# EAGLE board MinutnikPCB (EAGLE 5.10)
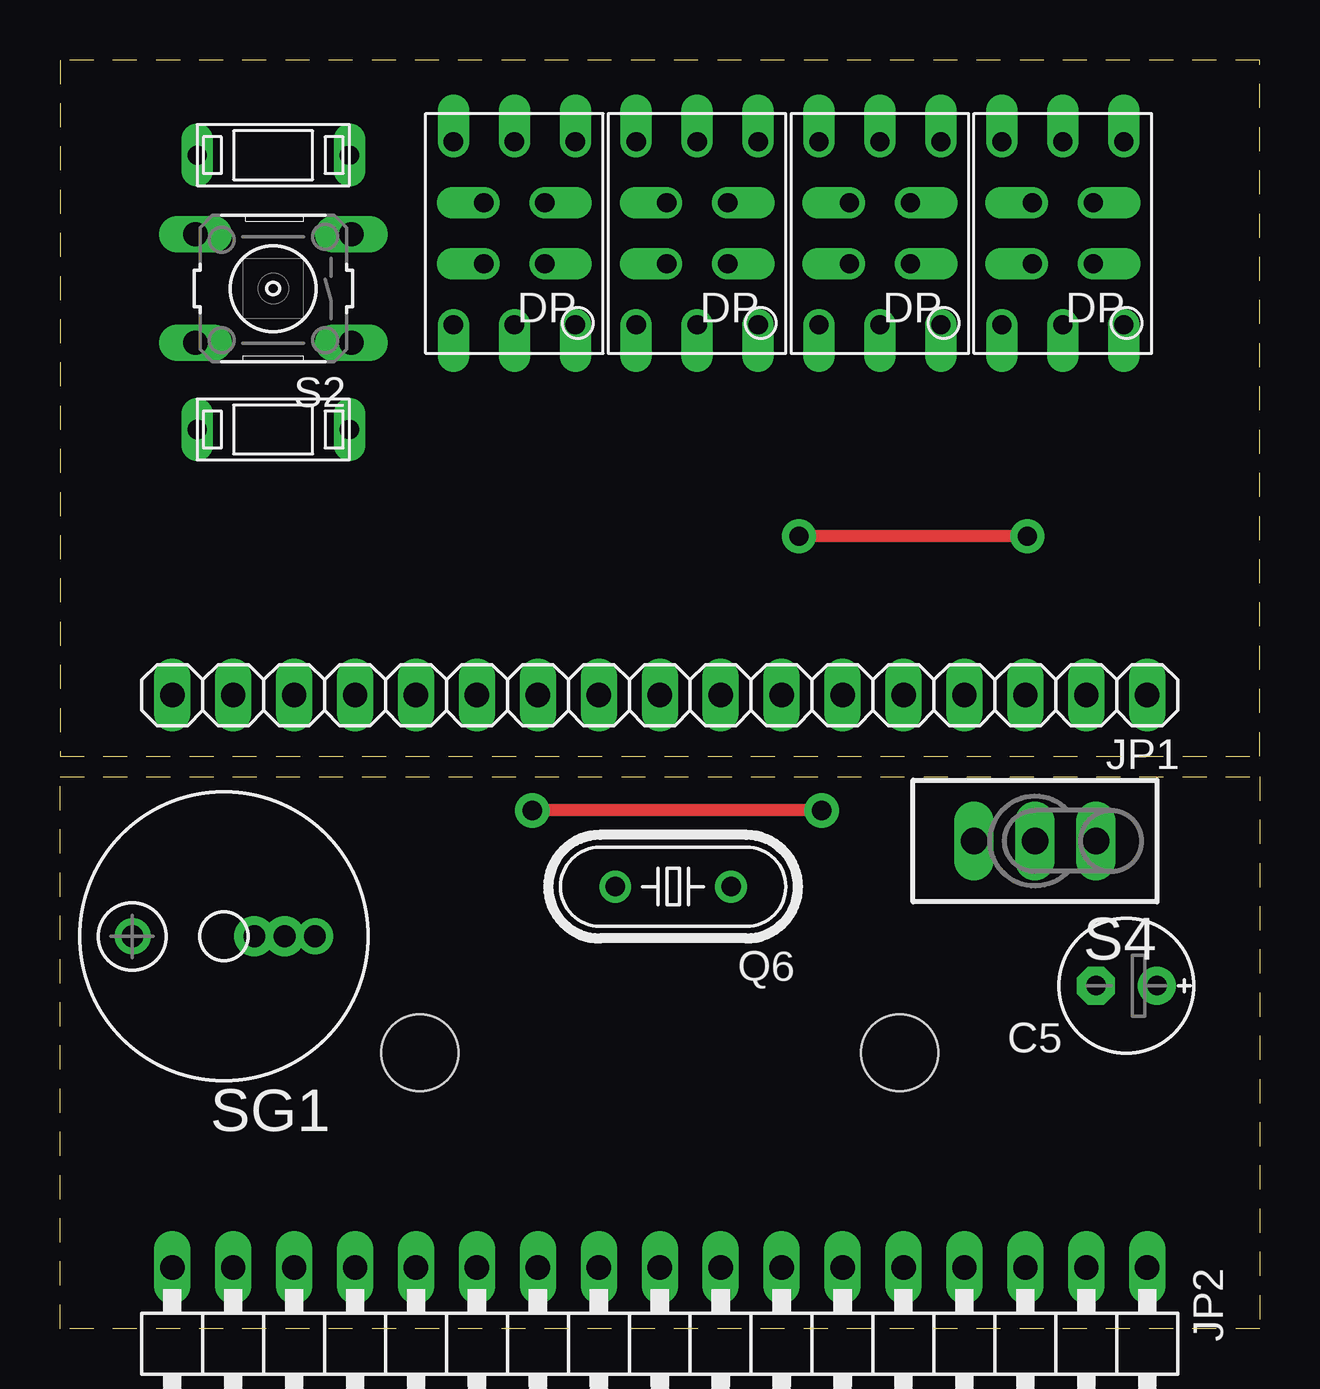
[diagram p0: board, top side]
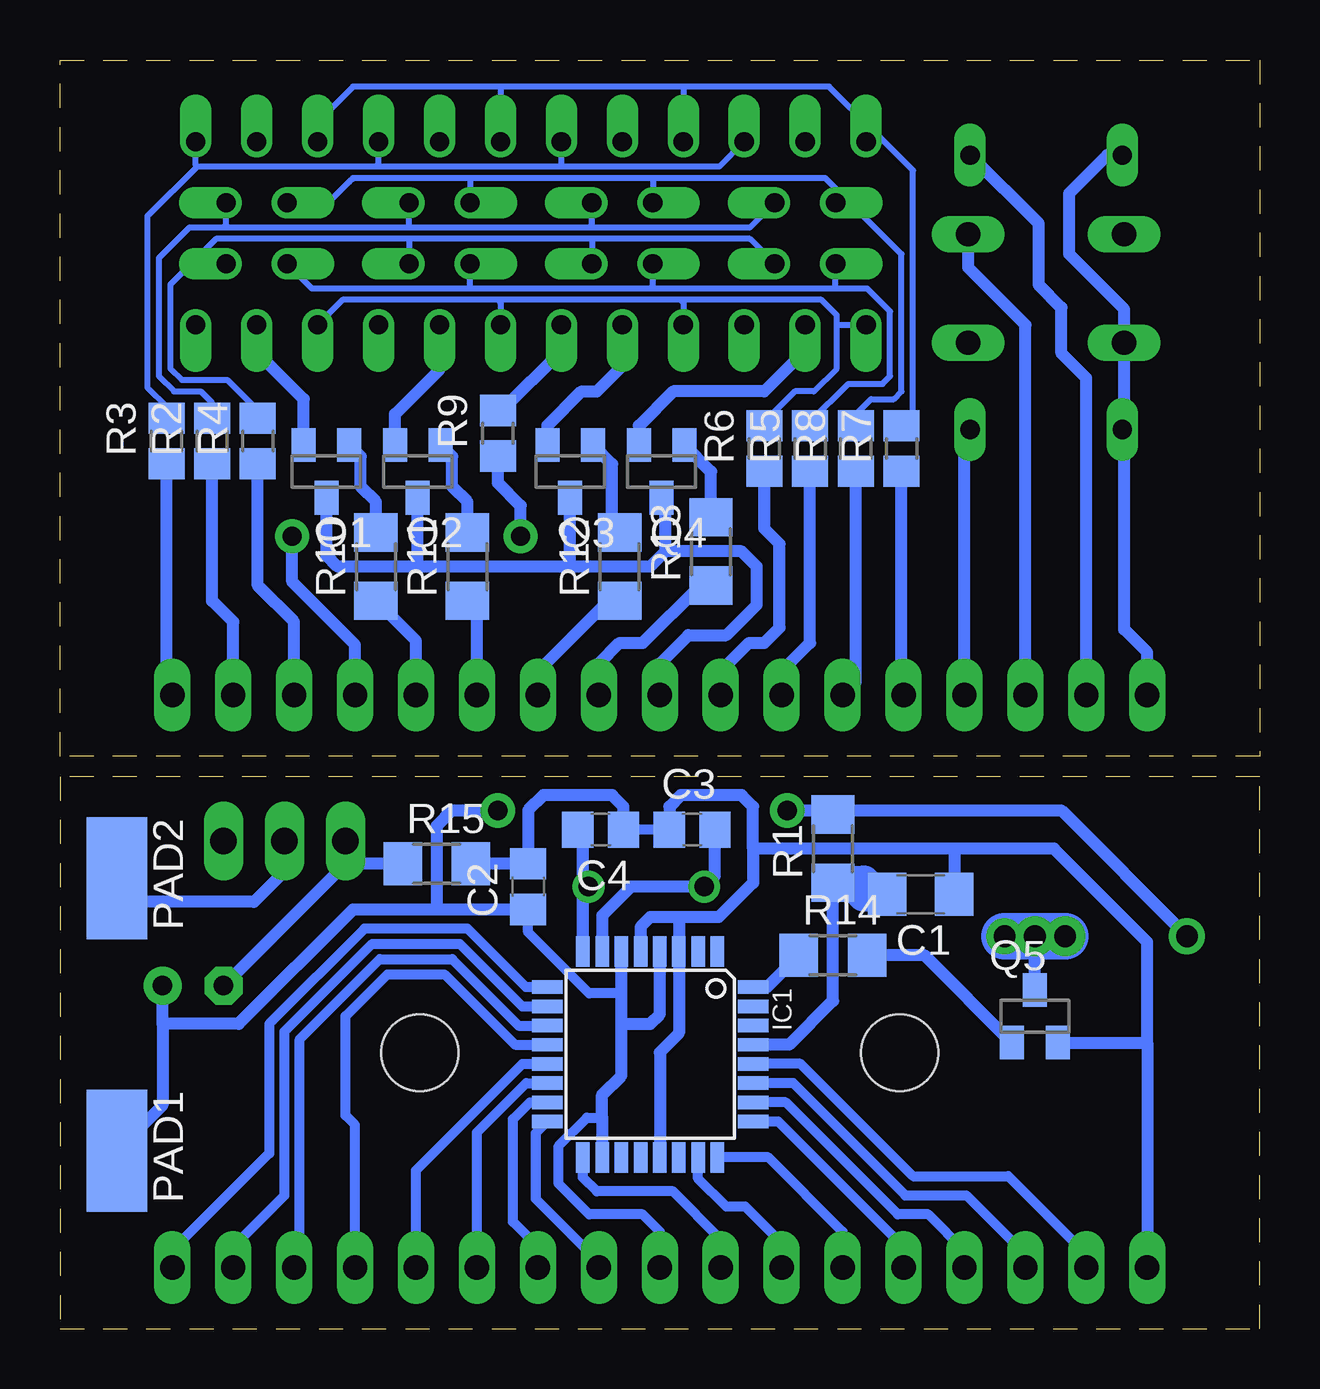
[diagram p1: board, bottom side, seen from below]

Size 50 x 52.86 mm. Coordinates in mm from the lower left corner, seen from the top.
Outline: 0,0 0,23 50,23 50,0 0,0
Outline: 0,23.86 50,23.86 50,52.86 0,52.86 0,23.86
Copper layers (1*16): Top 0.035mm / dielectric 1.5mm / Bottom 0.035mm
Design rules "default *": minimum track width 10mil, minimum drill 24mil, track to track 8mil, track to pad 8mil, pad to pad 8mil, via to via 8mil, smd to smd 8mil, copper to edge 5mil, drill to drill 8mil, minimum pad ring 10mil, minimum via ring 8mil, stop-mask expansion 4mil, vias tented up to drill 0mil, thermal gap 10mil
Holes 3.2 mm at 15,11.5 35,11.5

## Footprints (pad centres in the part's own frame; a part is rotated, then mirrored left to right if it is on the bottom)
C1206 = smd 1.6 x 1.8: 1 -1.4,0; 2 1.4,0
C0805 = smd 1.3 x 1.5: 1 -0.95,0; 2 0.95,0
E2,5-6E = drill 0.813 pad 1.575 round: + -1.27,0 | drill 0.813 pad 1.575 octagon: - 1.27,0
7MM = drill 0.8 pad 1.27 offset: 1 1.16,1.19; 2 2.43,3.73; 3 3.7,1.19; 4 4.97,3.73; 5 6.24,1.19; 6 6.24,8.81; 7 4.97,6.27; 8 3.7,8.81; 9 2.43,6.27; 10 1.16,8.81
TQFP32-08 = smd 1.27 x 0.559: 1 -4.293,2.8; 2 -4.293,2; 3 -4.293,1.2; 4 -4.293,0.4; 5 -4.293,-0.4; 6 -4.293,-1.2; 7 -4.293,-2; 8 -4.293,-2.8; 17 4.293,-2.8; 18 4.293,-2; 19 4.293,-1.2; 20 4.293,-0.4; 21 4.293,0.4; 22 4.293,1.2; 23 4.293,2; 24 4.293,2.8 | smd 0.559 x 1.27: 9 -2.8,-4.293; 10 -2,-4.293; 11 -1.2,-4.293; 12 -0.4,-4.293; 13 0.4,-4.293; 14 1.2,-4.293; 15 2,-4.293; 16 2.8,-4.293; 25 2.8,4.293; 26 2,4.293; 27 1.2,4.293; 28 0.4,4.293; 29 -0.4,4.293; 30 -1.2,4.293; 31 -2,4.293; 32 -2.8,4.293
1X17 = drill 1.016 long: 1 -20.32,0; 2 -17.78,0; 3 -15.24,0; 4 -12.7,0; 5 -10.16,0; 6 -7.62,0; 7 -5.08,0; 8 -2.54,0; 9 0,0; 10 2.54,0; 11 5.08,0; 12 7.62,0; 13 10.16,0; 14 12.7,0; 15 15.24,0; 16 17.78,0; 17 20.32,0
1X17/90 = drill 1.016 long: 1 -20.32,-3.81; 2 -17.78,-3.81; 3 -15.24,-3.81; 4 -12.7,-3.81; 5 -10.16,-3.81; 6 -7.62,-3.81; 7 -5.08,-3.81; 8 -2.54,-3.81; 9 0,-3.81; 10 2.54,-3.81; 11 5.08,-3.81; 12 7.62,-3.81; 13 10.16,-3.81; 14 12.7,-3.81; 15 15.24,-3.81; 16 17.78,-3.81; 17 20.32,-3.81
SMD2,54-5,08 = smd 2.54 x 5.08: 1 0,0
SOT23 = smd 1 x 1.4: 1 -0.95,-1.1; 2 0.95,-1.1; 3 0,1.1
HC49/S = drill 0.813 round: 1 -2.413,0; 2 2.413,0
R1206 = smd 1.6 x 1.803: 1 -1.422,0; 2 1.422,0
R0805 = smd 1.3 x 1.5: 1 -0.95,0; 2 0.95,0
MS = drill 0.8 long: 1 -2.54,0; 2 3.81,0
B3F-10XX = drill 1.016 long: 1 -3.251,2.261; 2 3.251,2.261; 3 -3.251,-2.261; 4 3.251,-2.261
TL3XPO = drill 1.1 pad 1.422 long: 1 -2.54,0; 2 0,0; 3 2.54,0
BMT1205XH7.5 = drill 0.9 pad 1.5 round: + 3.8,0; - -3.8,0

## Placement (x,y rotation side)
C1  100n  [C1206]  14.13,18.1 180 bottom
C2  100n  [C0805]  30.48,18.41 90 bottom
C3  27p  [C0805]  23.65,20.8 0 bottom
C4  27p  [C0805]  27.46,20.8 180 bottom
C5  100u  [E2,5-6E]  44.45,14.29 180 top
DIS1  7MM-CA  [7MM]  38.1,40.64 0 top
DIS2  7MM-CA  [7MM]  30.48,40.64 0 top
DIS3  7MM-CA  [7MM]  22.86,40.64 0 top
DIS4  7MM-CA  [7MM]  15.24,40.64 0 top
IC1  MEGA8-AI  [TQFP32-08]  25.4,11.43 270 bottom
JP1  [1X17]  25,26.4 180 top
JP2  [1X17/90]  25,-1.27 180 top
PAD1  [SMD2,54-5,08]  47.62,7.4 180 bottom
PAD2  [SMD2,54-5,08]  47.62,18.77 180 bottom
Q1  BC846  [SOT23]  38.89,35.72 180 bottom
Q2  BC846  [SOT23]  35.08,35.72 180 bottom
Q3  BC846  [SOT23]  28.73,35.72 180 bottom
Q4  BC846  [SOT23]  24.92,35.72 180 bottom
Q5  BC846  [SOT23]  9.37,13.02 0 bottom
Q6  8 MHz  [HC49/S]  25.56,18.41 180 top
R1  10k  [R1206]  17.78,20 90 bottom
R2  100  [R0805]  43.66,36.99 90 bottom
R3  100  [R0805]  45.56,36.99 90 bottom
R4  100  [R0805]  41.75,36.99 90 bottom
R5  100  [R0805]  18.73,36.67 90 bottom
R6  100  [R0805]  20.64,36.67 90 bottom
R7  100  [R0805]  14.92,36.67 90 bottom
R8  100  [R0805]  16.83,36.67 90 bottom
R9  100  [R0805]  31.75,37.31 90 bottom
R10  4k7  [R1206]  36.83,31.75 90 bottom
R11  4k7  [R1206]  33.02,31.75 90 bottom
R12  4k7  [R1206]  26.67,31.75 90 bottom
R13  4k7  [R1206]  22.86,32.38 90 bottom
R14  4k7  [R1206]  17.78,15.56 0 bottom
R15  0  [R1206]  34.29,19.37 0 bottom
S1  +  [MS]  9.53,37.47 180 top
S2  OK  [B3F-10XX]  8.89,43.34 180 top
S3  -  [MS]  9.53,48.89 180 top
S4  TL32PO  [TL3XPO]  40.64,20.32 180 top
SG1  Piezo  [BMT1205XH7.5]  6.83,16.35 180 top

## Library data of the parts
C1-C5 R1-R15 = rcl
DIS1-DIS4 = led-7-segment
IC1 = atmel
JP1 JP2 = pinhead
PAD1 PAD2 = wirepad
Q1-Q5 = transistor-npn
Q6 = crystal
S1-S3 = switch-omron
S4 = switch
SG1 = buzzer

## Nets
A: DIS1.7 DIS2.7 DIS3.7 DIS4.7 R2.2
A1: DIS1.3 Q1.2
A2: DIS2.3 Q2.2
A3: DIS3.3 Q3.2
A4: DIS4.3 Q4.2
B: DIS1.6 DIS2.6 DIS3.6 DIS4.6 R3.2
C: DIS1.4 DIS2.4 DIS3.4 DIS4.4 R4.2
COM: JP1.17 S1.2 S2.2 S3.2
D: DIS1.2 DIS2.2 DIS3.2 DIS4.2 R5.2
DP: DIS3.5 R9.2
E: DIS1.1 DIS2.1 DIS3.1 DIS4.1 R6.2
F: DIS1.10 DIS2.10 DIS3.10 DIS4.10 R7.2
G: DIS1.9 DIS2.9 DIS3.9 DIS4.9 R8.2
GND: C1.1 C2.2 C3.1 C4.1 IC1.3 IC1.5 IC1.21 JP2.17 Q5.2 R15.2
N$1: C1.2 IC1.29 R1.1
N$2: Q1.1 R10.2
N$3: Q2.1 R11.2
N$5: Q3.1 R12.2
N$6: Q4.1 R13.2
N$7: Q5.3 SG1.-
N$8: IC1.28 JP2.16
N$9: Q5.1 R14.2
N$10: JP1.1 R3.1
N$11: JP1.9 Q1.3 Q2.3 Q3.3 Q4.3
N$12: JP1.2 R2.1
N$13: JP1.3 R4.1
N$14: C3.2 IC1.7 Q6.2
N$15: C4.2 IC1.8 Q6.1
N$16: JP1.7 R12.1
N$17: JP1.5 R10.1
N$18: JP1.6 R11.1
N$19: JP1.8 R13.1
N$20: JP1.4 R9.1
N$21: JP1.10 R6.1
N$22: JP1.11 R5.1
N$23: JP1.12 R8.1
N$24: JP1.13 R7.1
N$25: IC1.27 JP2.15
N$26: IC1.26 JP2.14
N$27: IC1.25 JP2.13
N$28: IC1.24 JP2.12
N$29: IC1.23 JP2.11
N$30: IC1.9 JP2.1
N$31: IC1.10 JP2.2
N$32: IC1.11 JP2.3
N$33: IC1.12 JP2.4
N$34: IC1.13 JP2.5
N$35: IC1.14 JP2.6
N$36: IC1.15 JP2.7
N$37: IC1.17 JP2.10
N$38: IC1.16 JP2.8
N$39: PAD2.1 S4.2
N$40: IC1.32 R14.1
N$41: C5.- R15.1 S4.3
S1: JP1.14 S1.1
S2: JP1.15 S2.3
S3: JP1.16 S3.1
VCC: C2.1 C5.+ IC1.4 IC1.6 IC1.18 JP2.9 PAD1.1 R1.2 SG1.+

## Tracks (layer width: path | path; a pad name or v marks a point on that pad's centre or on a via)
A
  Bottom 0.254: 27.94,45.88 21.24,45.88 DIS4.7 | 27.94,45.88 35.4,45.88 | DIS3.7 27.83,45.99 27.94,45.88 | DIS2.7 35.45,45.93 35.4,45.88 | 35.4,45.88 43.18,45.88 | 43.18,45.88 44.61,45.88 45.88,44.61 45.88,39.69 45.24,39.05 44.13,39.05 43.66,38.58 R2.2 | DIS1.7 43.07,45.99 43.18,45.88
A1
  Bottom 0.508: Q1.2 39.84,38.73 41.8,40.69 DIS1.3
A2
  Bottom 0.508: Q2.2 36.03,38.1 34.18,39.96 DIS2.3
A3
  Bottom 0.508: Q3.2 29.68,37.63 28.26,39.05 27.62,39.05 26.56,40.11 DIS3.3
A4
  Bottom 0.508: DIS4.3 18.94,40.75 20.64,39.05 24.45,39.05 25.87,37.63 Q4.2
B
  Bottom 0.254: 29.05,48.42 22.51,48.42 DIS4.6 | 29.05,48.42 36.83,48.42 | DIS3.6 29.1,48.47 29.05,48.42 | DIS2.6 36.72,48.53 36.83,48.42 | 36.83,48.42 44.29,48.42 | 44.29,48.42 46.35,46.36 46.35,39.21 45.56,38.42 R3.2 | DIS1.6 44.34,48.47 44.29,48.42
C
  Bottom 0.254: 27.78,45.4 21.24,45.4 DIS4.4 | 27.78,45.4 35.4,45.4 | DIS3.4 27.83,45.35 27.78,45.4 | DIS2.4 35.45,45.35 35.4,45.4 | 35.4,45.4 43.5,45.4 44.13,44.77 | 44.13,44.77 45.4,43.5 45.4,40 44.93,39.53 43.02,39.53 41.75,38.26 R4.2 | DIS1.4 43.73,44.37 44.13,44.77
COM
  Bottom 0.508: S3.2 6.35,48.89 7.94,47.31 7.94,44.77 5.64,42.47 S2.2 5.64,37.47 | 5.64,37.47 S1.2 | 5.64,37.47 5.64,29.13 4.68,28.18 JP1.17
D
  Bottom 0.254: 25.4,43.34 32.86,43.34 | 32.86,43.34 39.5,43.34 DIS1.2 | DIS2.2 32.91,43.39 32.86,43.34 | DIS3.2 25.29,43.45 25.4,43.34 | 17.62,43.34 16.35,43.34 15.4,42.39 15.4,39.69 15.72,39.37 17.14,39.37 18.73,37.78 R5.2 | 17.62,43.34 25.4,43.34 | DIS4.2 17.67,43.39 17.62,43.34
DP
  Bottom 0.508: DIS3.5 29.1,40.75 31.59,38.26 R9.2
E
  Bottom 0.254: 24.13,42.86 31.75,42.86 | 31.75,42.86 38.23,42.86 DIS1.1 | DIS2.1 31.64,42.75 31.75,42.86 | DIS3.1 24.02,42.75 24.13,42.86 | 17.62,41.75 17.62,40 18.57,39.05 19.37,39.05 20.64,37.78 R6.2 | DIS4.1 17.54,41.83 17.62,41.75 | 24.13,42.86 18.26,42.86 17.62,42.23 17.62,41.75
F
  Bottom 0.254: 16.11,49.93 17.94,51.75 23.97,51.75 24.02,51.7 | 24.02,51.7 DIS3.10 | 16.11,49.93 14.45,48.26 14.45,38.1 R7.2 | DIS4.10 16.4,49.64 16.11,49.93 | DIS1.10 39.26,50.27 37.78,51.75 31.59,51.75 | 31.59,51.75 24.07,51.75 24.02,51.7 | DIS2.10 31.64,51.7 31.59,51.75
G
  Bottom 0.254: DIS1.9 38.81,46.91 37.94,47.78 | 37.94,47.78 | 37.94,47.78 37.78,47.94 32.86,47.94 | 25.24,47.94 32.86,47.94 | DIS3.9 25.29,47.89 25.24,47.94 | DIS2.9 32.91,47.89 32.86,47.94 | 25.24,47.94 18.1,47.94 17.38,47.23 | 17.38,47.23 14.92,44.77 14.92,39.05 15.24,38.73 16.19,38.73 16.83,38.1 R8.2 16.83,37.47 | DIS4.9 17.67,46.94 17.38,47.23
GND
  Bottom 0.406: C3.1 C4.1
  Bottom 0.508: 24.13,17.14 22.54,17.14 21.11,18.57 21.11,20 | 24.13,17.14 25.4,17.14 25.8,16.74 IC1.5 | 24.13,17.14 24.2,17.07 IC1.3 24.2,12.31 25,11.51 IC1.21 | 21.11,20 21.11,21.75 21.59,22.22 24.13,22.22 24.6,21.75 C3.1 | C4.1 26.51,21.75 26.99,22.22 29.84,22.22 30.48,21.59 C2.2 R15.2 | 12.54,20 21.11,20 | 4.68,11.92 JP2.17 | C1.1 12.73,19.87 12.54,20 | 12.54,20 8.57,20 4.68,16.11 4.68,11.92 | Q5.2 4.68,11.92
N$1
  Bottom 0.508: IC1.29 19.6,11.83 17.78,13.65 R1.1
  Bottom 1.422: R1.1 16.51,18.58 16.51,18.1 C1.2
N$2
  Bottom 0.508: Q1.1 37.47,36.34 37.47,35.08 36.83,34.45 R10.2
N$3
  Bottom 0.508: R11.2 33.02,34.45 33.66,35.08 33.66,36.34 Q2.1
N$5
  Bottom 0.508: Q3.1 26.99,36.02 26.99,33.49 R12.2
N$6
  Bottom 0.508: R13.2 22.86,35.7 Q4.1
N$7  (via drill 0.9 pad 1.68)
  Bottom 0.508: Q5.3 v9.37,16.35 | v9.37,16.35
  Bottom 1.93: SG1.- v8.1,16.35 | v8.1,16.35 | v9.37,16.35 SG1.- | SG1.-
N$8
  Bottom 0.406: IC1.28 19.13,11.03 14.45,6.35 10.48,6.35 7.22,3.09 JP2.16
N$9
  Bottom 0.508: R14.2 13.96,15.56 Q5.1
N$10
  Bottom 0.508: R3.1 45.56,25.64 JP1.1
N$11
  Bottom 0.508: Q1.3 38.89,34.94 38.89,32.23 38.42,31.75 35.08,31.75 | 35.08,31.75 Q2.3 | 35.08,31.75 | Q3.3 28.73,31.75 28.42,31.75 | 28.42,31.75 35.08,31.75 | JP1.9 25,27.7 23.81,28.89 22.23,28.89 20.95,30.16 20.95,31.75 21.59,32.38 24.77,32.38 | 28.42,31.75 25.4,31.75 24.77,32.38 | 24.77,32.38 24.77,34.46 Q4.3
N$12
  Bottom 0.508: R2.1 43.66,30.32 42.78,29.45 JP1.2
N$13
  Bottom 0.508: R4.1 41.75,30.96 40.24,29.45 JP1.3
N$14
  Bottom 0.508: IC1.7 27.4,17.21 26.19,18.41 Q6.2 22.7,18.86 C3.2
N$15
  Bottom 0.508: 28.2,18.41 28.2,20.58 C4.2 | IC1.8 28.2,18.41 | 28.2,18.41 Q6.1
N$16
  Bottom 0.508: 26.35,30.16 R12.1 27.14,30.33 30.08,27.39 JP1.7
N$17
  Bottom 0.508: JP1.5 35.16,28.66 R10.1
N$18
  Bottom 0.508: JP1.6 32.62,29.93 R11.1
N$19
  Bottom 0.508: JP1.8 27.54,27.7 26.67,28.57 25.72,28.57 23.33,30.96 R13.1
N$20  (via drill 0.8 pad 1.42)
  Top 0.508: v40.32,33.02 v30.8,33.02
  Bottom 0.508: R9.1 31.75,35.24 30.8,34.29 v30.8,33.02 | v40.32,33.02 40.32,31.12 37.7,28.49 JP1.4
N$21
  Bottom 0.508: JP1.10 22.46,27.39 21.27,28.57 20.64,28.57 20,29.21 20,32.7 20.64,33.34 R6.1
N$22
  Bottom 0.508: JP1.11 19.92,27.39 18.73,28.57 R5.1
N$23
  Bottom 0.508: R8.1 16.83,26.95 JP1.12
N$24
  Bottom 0.508: R7.1 14.92,25.48 JP1.13
N$25
  Bottom 0.406: IC1.27 19.44,10.23 14.76,5.56 12.22,5.56 9.76,3.09 JP2.15
N$26
  Bottom 0.406: IC1.26 19.75,9.43 15.08,4.76 13.81,4.76 12.3,3.25 JP2.14
N$27
  Bottom 0.406: JP2.13 14.84,3.41 20.06,8.63 IC1.25
N$28
  Bottom 0.406: JP2.12 17.38,4.04 20.47,7.14 IC1.24
N$29
  Bottom 0.406: IC1.23 23.4,6.25 22.23,5.08 21.43,5.08 19.92,3.57 JP2.11
N$30
  Bottom 0.406: IC1.9 30.58,14.23 33.02,16.67 37.31,16.67 41.27,12.7 41.27,7.3 45.32,3.26 JP2.1
N$31
  Bottom 0.406: IC1.10 30.73,13.43 33.34,16.03 36.99,16.03 40.64,12.38 40.64,5.56 42.78,3.42 JP2.2
N$32
  Bottom 0.406: IC1.11 30.89,12.63 33.66,15.4 36.67,15.4 40.01,12.06 40.01,3.81 40.24,3.57 JP2.3
N$33
  Bottom 0.406: IC1.12 31.04,11.83 33.97,14.76 36.35,14.76 38.1,13.02 38.1,8.89 37.7,8.49 JP2.4
N$34
  Bottom 0.406: IC1.13 30.72,11.03 35.16,6.59 JP2.5
N$35
  Bottom 0.406: JP2.6 32.62,8.18 30.57,10.23 IC1.14
N$36
  Bottom 0.406: IC1.15 30.42,9.43 31.11,8.73 31.11,4.45 30.08,3.41 JP2.7
N$37
  Bottom 0.406: JP2.10 22.46,3.73 24.45,5.71 27.62,5.71 28.2,6.29 IC1.17
N$38
  Bottom 0.406: IC1.16 30.16,8.16 30.16,5.4 27.54,2.77 JP2.8
N$39
  Bottom 0.508: S4.2 40.64,19.05 41.91,17.78 46.63,17.78 PAD2.1
N$40
  Bottom 0.508: IC1.32 20.53,14.23 R14.1
N$41
  Bottom 0.508: 38.1,19.37 S4.3 | R15.1 38.1,19.37 | 38.1,19.37 C5.-
S1
  Bottom 0.508: JP1.14 12.3,37.23 S1.1
S2
  Bottom 0.508: JP1.15 9.76,41.83 12.14,44.21 S2.3
S3
  Bottom 0.508: JP1.16 7.22,39.61 8.26,40.64 8.26,42.55 9.21,43.5 9.21,46.04 S3.1
VCC  (via drill 0.8 pad 1.42)
  Top 0.508: v31.75,21.59 v19.68,21.59
  Bottom 0.406: 27.4,8.79 28.04,8.79 29.21,7.62 29.21,6.03 27.94,4.76 25.72,4.76 25,4.04 JP2.9 | C2.1 30.48,16.51 27.94,13.97 26.6,13.97
  Bottom 0.508: 26.6,12.7 26.6,10.55 27.4,9.75 27.4,8.79 IC1.18 | 26.6,12.7 26.6,13.97 IC1.6 | IC1.4 25,13.1 25.4,12.7 26.6,12.7 | 34.29,17.46 37.78,17.46 42.55,12.7 45.72,12.7 | SG1.+ 8.27,21.59 17.78,21.59 | v19.68,21.59 17.78,21.59 | R1.2 17.61,21.43 17.78,21.59 | v31.75,21.59 33.66,21.59 34.29,20.95 34.29,17.46 | 34.29,17.46 C2.1 | 45.72,12.7 C5.+ | 45.72,12.7 45.72,9.31 PAD1.1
